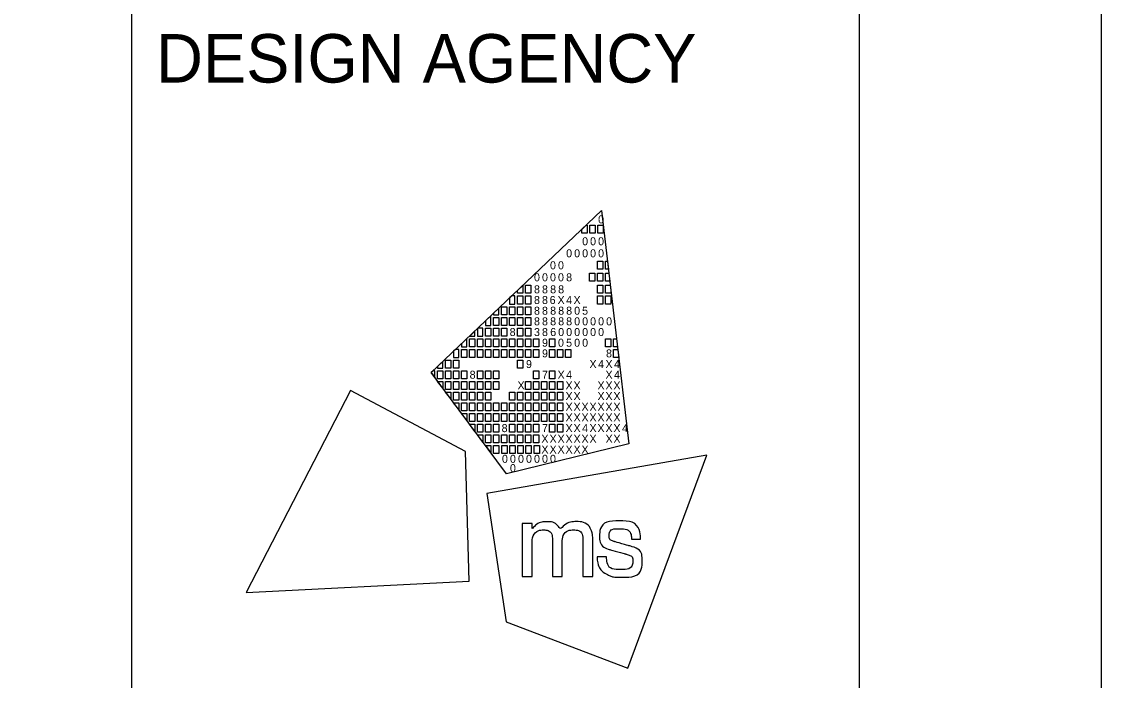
# Model space of a CAD drawing. Extents: x -0.3 to 34, y 0 to 22.
# Drawn here: x 31.772 to 34, y 3.617 to 4.976 of the extents above; entities that cross this region are included whole.
import ezdxf

# ---------------------------------------------------------------- set-up
doc = ezdxf.new("R2010")
doc.units = 0
for name, color, linetype in [('SH_Border', 7, 'Continuous'), ('SH_Cut_Line', 7, 'Continuous'), ('SH_Data', 7, 'Continuous')]:
    doc.layers.add(name, color=color, linetype=linetype)

msp = doc.modelspace()

# ---------------------------------------------------------------- linework, layer by layer
at = {"layer": 'SH_Border'}
for p, q in [((32, 0.5), (32, 21.5)), ((32.6175, 4.2519), (32.9688, 4.5861)), ((32.9688, 4.5861), (32.9688, 4.5861)), ((32.9688, 4.5861), (33.0253, 4.1052)), ((32.773, 4.043), (32.6175, 4.2519)), ((33.0253, 4.1052), (32.773, 4.043))]:
    msp.add_line(p, q, dxfattribs=at)
for points in [[(1.5, 21.5), (33.5, 21.5), (33.5, 0.5), (1.5, 0.5)], [(32.9279, 4.5472), (32.9369, 4.5558), (32.9389, 4.5558), (32.9389, 4.5393), (32.9279, 4.5393)], [(32.9444, 4.5558), (32.9554, 4.5558), (32.9554, 4.5393), (32.9444, 4.5393)], [(32.9609, 4.5558), (32.9719, 4.5558), (32.9719, 4.5393), (32.9609, 4.5393)], [(32.9606, 4.4815), (32.9716, 4.4815), (32.9716, 4.465), (32.9606, 4.465)], [(32.9771, 4.4815), (32.9811, 4.4815), (32.983, 4.465), (32.9771, 4.465)], [(32.9441, 4.4567), (32.9551, 4.4567), (32.9551, 4.4402), (32.9441, 4.4402)], [(32.9606, 4.4567), (32.9716, 4.4567), (32.9716, 4.4402), (32.9606, 4.4402)], [(32.9771, 4.4567), (32.984, 4.4567), (32.9859, 4.4402), (32.9771, 4.4402)], [(32.7953, 4.4211), (32.8064, 4.4316), (32.8064, 4.4154), (32.7953, 4.4154)], [(32.8123, 4.4319), (32.8233, 4.4319), (32.8233, 4.4154), (32.8123, 4.4154)], [(32.9606, 4.4319), (32.9716, 4.4319), (32.9716, 4.4154), (32.9606, 4.4154)], [(32.9771, 4.4319), (32.9869, 4.4319), (32.9881, 4.4218), (32.9881, 4.4154), (32.9771, 4.4154)], [(32.7958, 4.4099), (32.8068, 4.4099), (32.8068, 4.3934), (32.7958, 4.3934)], [(32.8123, 4.4099), (32.8233, 4.4099), (32.8233, 4.3934), (32.8123, 4.3934)], [(32.9606, 4.4099), (32.9716, 4.4099), (32.9716, 4.3934), (32.9606, 4.3934)], [(32.9771, 4.4099), (32.9881, 4.4099), (32.9881, 4.3934), (32.9771, 4.3934)], [(32.7627, 4.3879), (32.7737, 4.3879), (32.7737, 4.3714), (32.7627, 4.3714)], [(32.7793, 4.3879), (32.7903, 4.3879), (32.7903, 4.3714), (32.7793, 4.3714)], [(32.7958, 4.3879), (32.8068, 4.3879), (32.8068, 4.3714), (32.7958, 4.3714)], [(32.8123, 4.3879), (32.8233, 4.3879), (32.8233, 4.3714), (32.8123, 4.3714)], [(32.7297, 4.3439), (32.7407, 4.3439), (32.7407, 4.3273), (32.7297, 4.3273)], [(32.7462, 4.3659), (32.7572, 4.3659), (32.7572, 4.3494), (32.7462, 4.3494)], [(32.7462, 4.3439), (32.7572, 4.3439), (32.7572, 4.3273), (32.7462, 4.3273)], [(32.7627, 4.3659), (32.7737, 4.3659), (32.7737, 4.3494), (32.7627, 4.3494)], [(32.7627, 4.3439), (32.7737, 4.3439), (32.7737, 4.3273), (32.7627, 4.3273)], [(32.7793, 4.3659), (32.7903, 4.3659), (32.7903, 4.3494), (32.7793, 4.3494)], [(32.7958, 4.3659), (32.8068, 4.3659), (32.8068, 4.3494), (32.7958, 4.3494)], [(32.7958, 4.3439), (32.8068, 4.3439), (32.8068, 4.3273), (32.7958, 4.3273)], [(32.8123, 4.3659), (32.8233, 4.3659), (32.8233, 4.3494), (32.8123, 4.3494)], [(32.8123, 4.3439), (32.8233, 4.3439), (32.8233, 4.3273), (32.8123, 4.3273)], [(32.6967, 4.3218), (32.7077, 4.3218), (32.7077, 4.3053), (32.6967, 4.3053)], [(32.7132, 4.3218), (32.7242, 4.3218), (32.7242, 4.3053), (32.7132, 4.3053)], [(32.7297, 4.3218), (32.7407, 4.3218), (32.7407, 4.3053), (32.7297, 4.3053)], [(32.7462, 4.3218), (32.7572, 4.3218), (32.7572, 4.3053), (32.7462, 4.3053)], [(32.7627, 4.3218), (32.7737, 4.3218), (32.7737, 4.3053), (32.7627, 4.3053)], [(32.7793, 4.3218), (32.7903, 4.3218), (32.7903, 4.3053), (32.7793, 4.3053)], [(32.7958, 4.3218), (32.8068, 4.3218), (32.8068, 4.3053), (32.7958, 4.3053)], [(32.8123, 4.3218), (32.8233, 4.3218), (32.8233, 4.3053), (32.8123, 4.3053)], [(32.8288, 4.3218), (32.8398, 4.3218), (32.8398, 4.3053), (32.8288, 4.3053)], [(32.8618, 4.3218), (32.8728, 4.3218), (32.8728, 4.3053), (32.8618, 4.3053)], [(32.9771, 4.3218), (32.9881, 4.3218), (32.9881, 4.3053), (32.9771, 4.3053)], [(32.9935, 4.3218), (32.9998, 4.3218), (33.0018, 4.3053), (32.9935, 4.3053)], [(32.6802, 4.2998), (32.6912, 4.2998), (32.6912, 4.2833), (32.6802, 4.2833)], [(32.6967, 4.2998), (32.7077, 4.2998), (32.7077, 4.2833), (32.6967, 4.2833)], [(32.7132, 4.2998), (32.7242, 4.2998), (32.7242, 4.2833), (32.7132, 4.2833)], [(32.7297, 4.2998), (32.7407, 4.2998), (32.7407, 4.2833), (32.7297, 4.2833)], [(32.7462, 4.2998), (32.7572, 4.2998), (32.7572, 4.2833), (32.7462, 4.2833)], [(32.7627, 4.2998), (32.7737, 4.2998), (32.7737, 4.2833), (32.7627, 4.2833)], [(32.7793, 4.2998), (32.7903, 4.2998), (32.7903, 4.2833), (32.7793, 4.2833)], [(32.7958, 4.2998), (32.8068, 4.2998), (32.8068, 4.2833), (32.7958, 4.2833)], [(32.8123, 4.2998), (32.8233, 4.2998), (32.8233, 4.2833), (32.8123, 4.2833)], [(32.8288, 4.2998), (32.8398, 4.2998), (32.8398, 4.2833), (32.8288, 4.2833)], [(32.8618, 4.2998), (32.8728, 4.2998), (32.8728, 4.2833), (32.8618, 4.2833)], [(32.8783, 4.2998), (32.8893, 4.2998), (32.8893, 4.2833), (32.8783, 4.2833)], [(32.8947, 4.2998), (32.9057, 4.2998), (32.9057, 4.2833), (32.8947, 4.2833)], [(32.9935, 4.2998), (33.0024, 4.2998), (33.0044, 4.2833), (32.9935, 4.2833)], [(32.6471, 4.2778), (32.6581, 4.2778), (32.6581, 4.2613), (32.6471, 4.2613)], [(32.6637, 4.2778), (32.6747, 4.2778), (32.6747, 4.2613), (32.6637, 4.2613)], [(32.7958, 4.2778), (32.8068, 4.2778), (32.8068, 4.2613), (32.7958, 4.2613)], [(32.6306, 4.2558), (32.6416, 4.2558), (32.6416, 4.2393), (32.6306, 4.2393)], [(32.6471, 4.2558), (32.6581, 4.2558), (32.6581, 4.2393), (32.6471, 4.2393)], [(32.6637, 4.2558), (32.6747, 4.2558), (32.6747, 4.2393), (32.6637, 4.2393)], [(32.6802, 4.2558), (32.6912, 4.2558), (32.6912, 4.2393), (32.6802, 4.2393)], [(32.7132, 4.2558), (32.7242, 4.2558), (32.7242, 4.2393), (32.7132, 4.2393)], [(32.7297, 4.2558), (32.7407, 4.2558), (32.7407, 4.2393), (32.7297, 4.2393)], [(32.7462, 4.2558), (32.7572, 4.2558), (32.7572, 4.2393), (32.7462, 4.2393)], [(32.8288, 4.2558), (32.8398, 4.2558), (32.8398, 4.2393), (32.8288, 4.2393)], [(32.8618, 4.2558), (32.8728, 4.2558), (32.8728, 4.2393), (32.8618, 4.2393)], [(32.6306, 4.2338), (32.6416, 4.2338), (32.6416, 4.22)], [(32.6471, 4.2338), (32.6581, 4.2338), (32.6581, 4.2173), (32.6471, 4.2173)], [(32.6637, 4.2338), (32.6747, 4.2338), (32.6747, 4.2173), (32.6637, 4.2173)], [(32.6802, 4.2338), (32.6912, 4.2338), (32.6912, 4.2173), (32.6802, 4.2173)], [(32.6967, 4.2338), (32.7077, 4.2338), (32.7077, 4.2173), (32.6967, 4.2173)], [(32.7132, 4.2338), (32.7242, 4.2338), (32.7242, 4.2173), (32.7132, 4.2173)], [(32.7297, 4.2338), (32.7407, 4.2338), (32.7407, 4.2173), (32.7297, 4.2173)], [(32.7462, 4.2338), (32.7572, 4.2338), (32.7572, 4.2173), (32.7462, 4.2173)], [(32.8123, 4.2338), (32.8233, 4.2338), (32.8233, 4.2173), (32.8123, 4.2173)], [(32.8288, 4.2338), (32.8398, 4.2338), (32.8398, 4.2173), (32.8288, 4.2173)], [(32.8453, 4.2338), (32.8563, 4.2338), (32.8563, 4.2173), (32.8453, 4.2173)], [(32.8618, 4.2338), (32.8728, 4.2338), (32.8728, 4.2173), (32.8618, 4.2173)], [(32.8783, 4.2338), (32.8893, 4.2338), (32.8893, 4.2173), (32.8783, 4.2173)], [(32.6471, 4.2117), (32.6581, 4.2117), (32.6581, 4.198)], [(32.6637, 4.2117), (32.6747, 4.2117), (32.6747, 4.1952), (32.6637, 4.1952)], [(32.6802, 4.2117), (32.6912, 4.2117), (32.6912, 4.1952), (32.6802, 4.1952)], [(32.6967, 4.2117), (32.7077, 4.2117), (32.7077, 4.1952), (32.6967, 4.1952)], [(32.7132, 4.2117), (32.7242, 4.2117), (32.7242, 4.1952), (32.7132, 4.1952)], [(32.7297, 4.2117), (32.7407, 4.2117), (32.7407, 4.1952), (32.7297, 4.1952)], [(32.7793, 4.2117), (32.7903, 4.2117), (32.7903, 4.1952), (32.7793, 4.1952)], [(32.7958, 4.2117), (32.8068, 4.2117), (32.8068, 4.1952), (32.7958, 4.1952)], [(32.8123, 4.2117), (32.8233, 4.2117), (32.8233, 4.1952), (32.8123, 4.1952)], [(32.8288, 4.2117), (32.8398, 4.2117), (32.8398, 4.1952), (32.8288, 4.1952)], [(32.8453, 4.2117), (32.8563, 4.2117), (32.8563, 4.1952), (32.8453, 4.1952)], [(32.8618, 4.2117), (32.8728, 4.2117), (32.8728, 4.1952), (32.8618, 4.1952)], [(32.8783, 4.2117), (32.8893, 4.2117), (32.8893, 4.1952), (32.8783, 4.1952)], [(32.6637, 4.1897), (32.6747, 4.1897), (32.6747, 4.176)], [(32.6747, 4.1897), (32.6747, 4.1897), (32.6747, 4.1897)], [(32.6802, 4.1897), (32.6912, 4.1897), (32.6912, 4.1732), (32.6802, 4.1732)], [(32.6967, 4.1897), (32.7077, 4.1897), (32.7077, 4.1732), (32.6967, 4.1732)], [(32.7132, 4.1897), (32.7242, 4.1897), (32.7242, 4.1732), (32.7132, 4.1732)], [(32.7297, 4.1897), (32.7407, 4.1897), (32.7407, 4.1732), (32.7297, 4.1732)], [(32.7462, 4.1897), (32.7572, 4.1897), (32.7572, 4.1732), (32.7462, 4.1732)], [(32.7627, 4.1897), (32.7737, 4.1897), (32.7737, 4.1732), (32.7627, 4.1732)], [(32.7793, 4.1897), (32.7903, 4.1897), (32.7903, 4.1732), (32.7793, 4.1732)], [(32.7958, 4.1897), (32.8068, 4.1897), (32.8068, 4.1732), (32.7958, 4.1732)], [(32.8123, 4.1897), (32.8233, 4.1897), (32.8233, 4.1732), (32.8123, 4.1732)], [(32.8288, 4.1897), (32.8398, 4.1897), (32.8398, 4.1732), (32.8288, 4.1732)], [(32.8453, 4.1897), (32.8563, 4.1897), (32.8563, 4.1732), (32.8453, 4.1732)], [(32.8618, 4.1897), (32.8728, 4.1897), (32.8728, 4.1732), (32.8618, 4.1732)], [(32.8783, 4.1897), (32.8893, 4.1897), (32.8893, 4.1732), (32.8783, 4.1732)], [(32.6802, 4.1677), (32.6912, 4.1677), (32.6912, 4.154)], [(32.6967, 4.1677), (32.7077, 4.1677), (32.7077, 4.1512), (32.6967, 4.1512)], [(32.7132, 4.1677), (32.7242, 4.1677), (32.7242, 4.1512), (32.7132, 4.1512)], [(32.7297, 4.1677), (32.7407, 4.1677), (32.7407, 4.1512), (32.7297, 4.1512)], [(32.7462, 4.1677), (32.7572, 4.1677), (32.7572, 4.1512), (32.7462, 4.1512)], [(32.7627, 4.1677), (32.7737, 4.1677), (32.7737, 4.1512), (32.7627, 4.1512)], [(32.7793, 4.1677), (32.7903, 4.1677), (32.7903, 4.1512), (32.7793, 4.1512)], [(32.7958, 4.1677), (32.8068, 4.1677), (32.8068, 4.1512), (32.7958, 4.1512)], [(32.8123, 4.1677), (32.8233, 4.1677), (32.8233, 4.1512), (32.8123, 4.1512)], [(32.8288, 4.1677), (32.8398, 4.1677), (32.8398, 4.1512), (32.8288, 4.1512)], [(32.8453, 4.1677), (32.8563, 4.1677), (32.8563, 4.1512), (32.8453, 4.1512)], [(32.8618, 4.1677), (32.8728, 4.1677), (32.8728, 4.1512), (32.8618, 4.1512)], [(32.8783, 4.1677), (32.8893, 4.1677), (32.8893, 4.1512), (32.8783, 4.1512)], [(32.7077, 4.1305), (32.6965, 4.1457), (32.7077, 4.1457)], [(32.7132, 4.1457), (32.7242, 4.1457), (32.7242, 4.1292), (32.7132, 4.1292)], [(32.7297, 4.1457), (32.7407, 4.1457), (32.7407, 4.1292), (32.7297, 4.1292)], [(32.7462, 4.1457), (32.7572, 4.1457), (32.7572, 4.1292), (32.7462, 4.1292)], [(32.7793, 4.1457), (32.7903, 4.1457), (32.7903, 4.1292), (32.7793, 4.1292)], [(32.7958, 4.1457), (32.8068, 4.1457), (32.8068, 4.1292), (32.7958, 4.1292)], [(32.8123, 4.1457), (32.8233, 4.1457), (32.8233, 4.1292), (32.8123, 4.1292)], [(32.8288, 4.1457), (32.8398, 4.1457), (32.8398, 4.1292), (32.8288, 4.1292)], [(32.8618, 4.1457), (32.8728, 4.1457), (32.8728, 4.1292), (32.8618, 4.1292)], [(32.8783, 4.1457), (32.8893, 4.1457), (32.8893, 4.1292), (32.8783, 4.1292)], [(32.724, 4.1082), (32.7132, 4.1237), (32.7242, 4.1237)], [(32.7297, 4.1237), (32.7407, 4.1237), (32.7407, 4.1072), (32.7297, 4.1072)], [(32.7462, 4.1237), (32.7572, 4.1237), (32.7572, 4.1072), (32.7462, 4.1072)], [(32.7627, 4.1237), (32.7737, 4.1237), (32.7737, 4.1072), (32.7627, 4.1072)], [(32.7793, 4.1237), (32.7903, 4.1237), (32.7903, 4.1072), (32.7793, 4.1072)], [(32.7958, 4.1237), (32.8068, 4.1237), (32.8068, 4.1072), (32.7958, 4.1072)], [(32.8123, 4.1237), (32.8233, 4.1237), (32.8233, 4.1072), (32.8123, 4.1072)], [(32.8288, 4.1237), (32.8398, 4.1237), (32.8398, 4.1072), (32.8288, 4.1072)], [(32.7302, 4.1017), (32.7407, 4.1017), (32.7408, 4.0875)], [(32.7463, 4.1017), (32.7573, 4.1017), (32.7573, 4.0852), (32.7463, 4.0852)], [(32.763, 4.1017), (32.774, 4.1017), (32.774, 4.0852), (32.763, 4.0852)], [(32.7794, 4.1017), (32.7904, 4.1017), (32.7904, 4.0852), (32.7794, 4.0852)], [(32.796, 4.1017), (32.807, 4.1017), (32.807, 4.0852), (32.796, 4.0852)], [(32.8129, 4.1017), (32.8239, 4.1017), (32.8239, 4.0851), (32.8129, 4.0851)], [(32.8296, 4.1017), (32.8406, 4.1017), (32.8406, 4.0851), (32.8296, 4.0851)]]:
    msp.add_lwpolyline(points, close=True, dxfattribs=at)
for points in [[(32.7903, 4.4099), (32.7836, 4.4099), (32.7793, 4.4058), (32.7793, 4.3934), (32.7903, 4.3934), (32.7903, 4.4099)], [(32.7407, 4.3691), (32.7297, 4.3587), (32.7297, 4.3494), (32.7407, 4.3494), (32.7407, 4.3691)], [(32.7572, 4.3849), (32.7462, 4.3744), (32.7462, 4.3714), (32.7572, 4.3714), (32.7572, 4.3849)], [(32.7242, 4.3439), (32.7141, 4.3439), (32.7132, 4.343), (32.7132, 4.3273), (32.7242, 4.3273), (32.7242, 4.3439)], [(32.6912, 4.322), (32.6802, 4.3115), (32.6802, 4.3053), (32.6912, 4.3053), (32.6912, 4.322)], [(32.7077, 4.3377), (32.6968, 4.3273), (32.7077, 4.3273), (32.7077, 4.3377)], [(32.6747, 4.2998), (32.6679, 4.2998), (32.6637, 4.2958), (32.6637, 4.2833), (32.6747, 4.2833), (32.6747, 4.2998)], [(32.6251, 4.2558), (32.6216, 4.2558), (32.6175, 4.2519), (32.6251, 4.2417), (32.6251, 4.2558)], [(32.6416, 4.2749), (32.6306, 4.2644), (32.6306, 4.2613), (32.6416, 4.2613), (32.6416, 4.2749)], [(32.4512, 4.2149), (32.2359, 3.7988), (32.6956, 3.8215), (32.6884, 4.0892), (32.4512, 4.2149)], [(33.0229, 3.6422), (33.1859, 4.0814), (32.7324, 4.0029), (32.7722, 3.7381), (33.0229, 3.6422)]]:
    msp.add_lwpolyline(points, dxfattribs=at)
for points in [[(32.8048, 3.8315), (32.8048, 3.8315), (32.8048, 3.9409), (32.8048, 3.9409), (32.8048, 3.9409), (32.8255, 3.9409), (32.8255, 3.9409), (32.8255, 3.9409), (32.8255, 3.9297), (32.8255, 3.9297), (32.8346, 3.9399), (32.8457, 3.9445), (32.8555, 3.9445), (32.8688, 3.9445), (32.8791, 3.9372), (32.8837, 3.9266), (32.8915, 3.9381), (32.905, 3.9446), (32.9166, 3.9446), (32.9325, 3.9446), (32.9451, 3.935), (32.9494, 3.9213), (32.9494, 3.9212), (32.9494, 3.9212), (32.9494, 3.9212), (32.9501, 3.919), (32.9506, 3.9172), (32.9506, 3.9071), (32.9506, 3.9071), (32.9506, 3.8314), (32.9506, 3.8314), (32.9506, 3.8314), (32.9303, 3.8314), (32.9303, 3.8314), (32.9303, 3.8314), (32.9303, 3.9048), (32.9303, 3.9048), (32.9303, 3.9201), (32.9219, 3.9274), (32.911, 3.9274), (32.8995, 3.9274), (32.8879, 3.9171), (32.8879, 3.9001), (32.8879, 3.9001), (32.8879, 3.8315), (32.8879, 3.8315), (32.8879, 3.8315), (32.8674, 3.8315), (32.8674, 3.8315), (32.8674, 3.8315), (32.8674, 3.9059), (32.8674, 3.9059), (32.8674, 3.9203), (32.8588, 3.9274), (32.8496, 3.9274), (32.8384, 3.9274), (32.8254, 3.917), (32.8254, 3.8962), (32.8254, 3.8962), (32.8254, 3.8315), (32.8254, 3.8315), (32.8254, 3.8315), (32.8048, 3.8315), (32.8048, 3.8315)], [(32.9595, 3.8709), (32.9595, 3.8709), (32.9595, 3.8717), (32.9595, 3.8717), (32.9595, 3.8717), (32.9603, 3.8717), (32.9603, 3.8717), (32.9603, 3.8717), (32.9783, 3.8717), (32.9783, 3.8717), (32.9783, 3.8717), (32.9789, 3.8717), (32.9789, 3.8717), (32.9789, 3.8717), (32.979, 3.871), (32.979, 3.871), (32.9803, 3.8554), (32.9887, 3.846), (33.009, 3.846), (33.0273, 3.846), (33.0333, 3.8554), (33.0333, 3.8631), (33.0333, 3.8732), (33.0256, 3.8758), (33.0175, 3.878), (33.0175, 3.878), (32.987, 3.8867), (32.987, 3.8867), (32.972, 3.8909), (32.9648, 3.9019), (32.9648, 3.9142), (32.9648, 3.9303), (32.9768, 3.9462), (33.0052, 3.9462), (33.0348, 3.9462), (33.0489, 3.9285), (33.0489, 3.9095), (33.0489, 3.9095), (33.0489, 3.9087), (33.0489, 3.9087), (33.0489, 3.9087), (33.0482, 3.9087), (33.0482, 3.9087), (33.0482, 3.9087), (33.0312, 3.9087), (33.0312, 3.9087), (33.0312, 3.9087), (33.0305, 3.9087), (33.0305, 3.9087), (33.0305, 3.9087), (33.0305, 3.9094), (33.0305, 3.9094), (33.0301, 3.9208), (33.0226, 3.93), (33.0056, 3.93), (32.9891, 3.93), (32.9843, 3.9218), (32.9843, 3.9157), (32.9843, 3.9108), (32.9869, 3.9059), (32.9959, 3.9033), (32.9959, 3.9033), (33.0255, 3.8948), (33.0255, 3.8948), (33.0462, 3.8889), (33.0527, 3.8777), (33.0527, 3.8639), (33.0527, 3.8462), (33.041, 3.8298), (33.0087, 3.8298), (32.9952, 3.8298), (32.9877, 3.8321), (32.9823, 3.8348), (32.969, 3.8414), (32.9609, 3.8536), (32.9595, 3.8709)]]:
    msp.add_open_spline(points, degree=3, dxfattribs=at)
at = {"layer": 'SH_Cut_Line'}
msp.add_lwpolyline([(0, 0), (34, 0), (34, 22), (0, 22)], close=True, dxfattribs=at)
at = {"layer": 'SH_Data'}
msp.add_line((32.75, 4), (32.75, 4), dxfattribs=at)

# ---------------------------------------------------------------- texts
at = {"layer": 'SH_Border'}
for s, p in [('0', (32.9617, 4.5597)), ('0', (32.9288, 4.5145)), ('0', (32.9452, 4.5145)), ('0', (32.9617, 4.5145)), ('0', (32.8958, 4.4897)), ('0', (32.9123, 4.4897)), ('0', (32.9288, 4.4897)), ('0', (32.9452, 4.4897)), ('0', (32.9617, 4.4897)), ('0', (32.8625, 4.465)), ('0', (32.879, 4.465)), ('0', (32.8295, 4.4402)), ('0', (32.846, 4.4402)), ('0', (32.8625, 4.4402)), ('0', (32.879, 4.4402)), ('8', (32.8958, 4.4402)), ('8', (32.8295, 4.4154)), ('8', (32.846, 4.4154)), ('8', (32.8628, 4.4154)), ('8', (32.8793, 4.4154)), ('8', (32.8295, 4.3934)), ('8', (32.846, 4.3934)), ('6', (32.8618, 4.3934)), ('X', (32.8781, 4.3934)), ('4', (32.8958, 4.3934)), ('X', (32.911, 4.3934)), ('8', (32.8295, 4.3713)), ('8', (32.8295, 4.3494)), ('8', (32.846, 4.3713)), ('8', (32.846, 4.3494)), ('8', (32.8628, 4.3713)), ('8', (32.8628, 4.3494)), ('8', (32.8794, 4.3713)), ('8', (32.8794, 4.3494)), ('8', (32.8958, 4.3713)), ('8', (32.8958, 4.3494)), ('0', (32.9123, 4.3713)), ('0', (32.9123, 4.3494)), ('5', (32.9287, 4.3713)), ('0', (32.9288, 4.3494)), ('0', (32.9452, 4.3494)), ('0', (32.9617, 4.3494)), ('0', (32.9782, 4.3494)), ('8', (32.7793, 4.3273)), ('3', (32.8295, 4.3273)), ('8', (32.846, 4.3273)), ('6', (32.8629, 4.3273)), ('0', (32.8793, 4.3273)), ('0', (32.8958, 4.3273)), ('0', (32.9123, 4.3273)), ('0', (32.9288, 4.3273)), ('0', (32.9452, 4.3273)), ('0', (32.9617, 4.3273)), ('9', (32.846, 4.3053)), ('0', (32.879, 4.3053)), ('5', (32.8957, 4.3053)), ('0', (32.9123, 4.3053)), ('0', (32.9288, 4.3053)), ('9', (32.846, 4.2833)), ('8', (32.9781, 4.2833)), ('9', (32.813, 4.2613)), ('X', (32.9439, 4.2613)), ('4', (32.9617, 4.2613)), ('X', (32.9769, 4.2613)), ('4', (32.9946, 4.2613)), ('8', (32.6967, 4.2393)), ('7', (32.846, 4.2393)), ('X', (32.8781, 4.2393)), ('4', (32.8958, 4.2393)), ('X', (32.9769, 4.2393)), ('4', (32.9946, 4.2393)), ('X', (32.7955, 4.2173)), ('X', (32.8945, 4.2173)), ('X', (32.911, 4.2173)), ('X', (32.9604, 4.2173)), ('X', (32.9769, 4.2173)), ('X', (32.9933, 4.2173)), ('X', (32.8945, 4.1952)), ('X', (32.911, 4.1952)), ('X', (32.9604, 4.1952)), ('X', (32.9769, 4.1952)), ('X', (32.9933, 4.1952)), ('X', (32.8945, 4.1732)), ('X', (32.911, 4.1732)), ('X', (32.9274, 4.1732)), ('X', (32.9439, 4.1732)), ('X', (32.9604, 4.1732)), ('X', (32.9769, 4.1732)), ('X', (32.9933, 4.1732)), ('X', (32.8945, 4.1512)), ('X', (32.911, 4.1512)), ('X', (32.9274, 4.1512)), ('X', (32.9439, 4.1512)), ('X', (32.9604, 4.1512)), ('X', (32.9769, 4.1512)), ('X', (32.9933, 4.1512)), ('8', (32.7627, 4.1292)), ('7', (32.846, 4.1292)), ('X', (32.8945, 4.1292)), ('X', (32.911, 4.1292)), ('4', (32.9288, 4.1292)), ('X', (32.9439, 4.1292)), ('X', (32.9604, 4.1292)), ('X', (32.9769, 4.1292)), ('X', (32.9933, 4.1292)), ('4', (33.0111, 4.1292)), ('X', (32.8447, 4.1072)), ('X', (32.8616, 4.1072)), ('X', (32.878, 4.1072)), ('X', (32.8945, 4.1072)), ('X', (32.911, 4.1072)), ('X', (32.9274, 4.1072)), ('X', (32.9439, 4.1072)), ('X', (32.9771, 4.1072)), ('X', (32.9933, 4.1072)), ('X', (32.8447, 4.0851)), ('X', (32.8616, 4.0851)), ('X', (32.878, 4.0851)), ('X', (32.8945, 4.0851)), ('X', (32.911, 4.0851)), ('X', (32.9274, 4.0851)), ('0', (32.7634, 4.0659)), ('0', (32.7799, 4.0659)), ('0', (32.7965, 4.0659)), ('0', (32.813, 4.0659)), ('0', (32.8295, 4.0659)), ('0', (32.846, 4.0659)), ('0', (32.8625, 4.0659)), ('0', (32.7799, 4.0467))]:
    msp.add_text(s, height=0.0165, rotation=360, dxfattribs=at).set_placement(p)
at = {"layer": 'SH_Data'}
msp.add_text('DESIGN AGENCY', height=0.1, dxfattribs=at).set_placement((32.05, 4.85))

doc.saveas('drawing.dxf')
